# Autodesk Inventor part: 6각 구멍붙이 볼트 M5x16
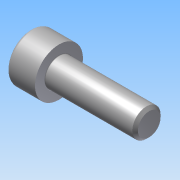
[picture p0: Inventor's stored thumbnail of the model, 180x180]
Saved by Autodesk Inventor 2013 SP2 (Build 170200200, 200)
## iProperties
Created: 2026-10
Part Number: 6각 구멍붙이 볼트 M5x16
Material: Generic
Document SubType Name: Modeling
Designer: a
Density: 1 g/cm^3
Author: a
변환 표준: STEP AP214IS
전처리기: Build: 200, Release: 2013 SP2 Update 6 - Date: Thu 07/17/2014
전송 단위: 밀리미터
불확실성: 0.01
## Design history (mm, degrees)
node "6각 구멍붙이 볼트 M5x161"
body "Solid1"
node "기준1"
